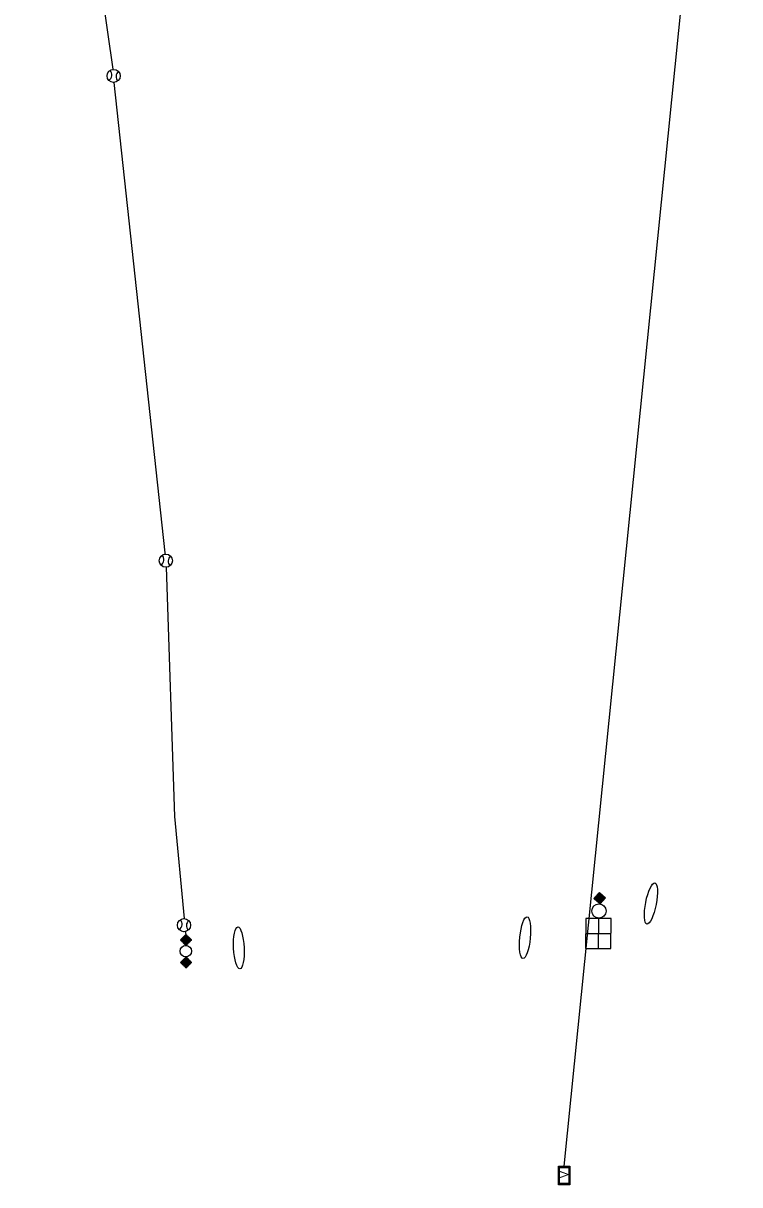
# Model space of a CAD drawing. Extents: x 584850 to 602551, y 145475 to 158627.
# Drawn here: x 594140 to 594577, y 153187 to 153895 of the extents above; entities that cross this region are included whole.
import ezdxf

# ---------------------------------------------------------------- set-up
doc = ezdxf.new("R2010")
doc.units = 0
doc.layers.add('B_MISC', color=7, linetype='Continuous')
doc.layers.add('E_RDWY', color=7, linetype='Continuous')

# ---------------------------------------------------------------- blocks, each defined once
blk = doc.blocks.new('PB24X42')
at = {"layer": 'E_RDWY'}
blk.add_circle((0, 0), 2, dxfattribs=at)
for centre, start, end in [((-2.59, 0.09), 308.3742, 47.6044), ((2.73, 0.07), 134.4184, 228.4474)]:
    blk.add_arc(centre, 2, start, end, dxfattribs=at)

msp = doc.modelspace()

# ---------------------------------------------------------------- linework, layer by layer
at = {"layer": 'B_MISC'}
for p, q in [((594469.73, 153198.28), (594576.82, 154259.36)), ((594194.8, 153867.11), (594139.91, 154245.19)), ((594226.44, 153572.23), (594195.44, 153859.06)), ((594232.36, 153411.51), (594227.19, 153563.53)), ((594238.28, 153349.25), (594232.36, 153411.51)), ((594238.65, 153341.41), (594239.15, 153339.63))]:
    msp.add_line(p, q, dxfattribs=at)
msp.add_arc((594176.91, 153565.37), 50, 7.0373, 7.8773, dxfattribs=at)
at = {"layer": 'E_RDWY'}
for p, q in [((594487.9, 153361.49), (594494.96, 153361.96)), ((594488.18, 153361.81), (594494.64, 153362.24)), ((594488.22, 153361.21), (594488.18, 153361.81)), ((594488.46, 153362.13), (594494.32, 153362.52)), ((594488.54, 153360.93), (594488.46, 153362.13)), ((594488.74, 153362.45), (594494, 153362.8)), ((594488.86, 153360.65), (594488.74, 153362.45)), ((594489.02, 153362.77), (594493.68, 153363.07)), ((594489.18, 153360.37), (594489.02, 153362.77)), ((594489.3, 153363.08), (594493.36, 153363.35)), ((594489.5, 153360.09), (594489.3, 153363.08)), ((594489.58, 153363.4), (594493.04, 153363.63)), ((594489.82, 153359.81), (594489.58, 153363.4)), ((594489.86, 153363.72), (594492.72, 153363.91)), ((594490.14, 153359.53), (594489.86, 153363.72)), ((594490.14, 153364.04), (594492.41, 153364.19)), ((594490.46, 153359.25), (594490.14, 153364.04)), ((594490.42, 153364.36), (594492.09, 153364.47)), ((594490.78, 153358.97), (594490.42, 153364.36)), ((594490.7, 153364.68), (594491.77, 153364.75)), ((594491.1, 153358.69), (594490.7, 153364.68)), ((594490.98, 153365), (594491.45, 153365.03)), ((594491.42, 153358.41), (594490.98, 153365)), ((594491.73, 153358.26), (594491.27, 153365.19)), ((594492.01, 153358.58), (594491.58, 153364.91)), ((594492.29, 153358.9), (594491.9, 153364.63)), ((594492.56, 153359.22), (594492.22, 153364.35)), ((594492.84, 153359.54), (594492.54, 153364.07)), ((594493.12, 153359.86), (594492.86, 153363.79)), ((594493.4, 153360.18), (594493.18, 153363.51)), ((594493.68, 153360.5), (594493.5, 153363.23)), ((594493.96, 153360.82), (594493.82, 153362.95)), ((594494.24, 153361.14), (594494.14, 153362.68)), ((594494.52, 153361.46), (594494.46, 153362.4)), ((594494.8, 153361.77), (594494.78, 153362.12)), ((594488.22, 153361.21), (594494.68, 153361.64)), ((594488.54, 153360.93), (594494.4, 153361.32)), ((594488.86, 153360.65), (594494.12, 153361)), ((594489.18, 153360.37), (594493.84, 153360.68)), ((594489.5, 153360.09), (594493.56, 153360.36)), ((594489.82, 153359.81), (594493.28, 153360.04)), ((594490.14, 153359.53), (594493, 153359.72)), ((594490.46, 153359.25), (594492.72, 153359.4)), ((594490.78, 153358.97), (594492.44, 153359.08)), ((594491.1, 153358.69), (594492.16, 153358.76)), ((594491.42, 153358.41), (594491.89, 153358.45)), ((594490.61, 153349.35), (594490.53, 153331)), ((594235.82, 153336.17), (594242.49, 153336.17)), ((594235.99, 153336.46), (594235.99, 153336.01)), ((594235.99, 153336.46), (594242.32, 153336.46)), ((594236.11, 153335.88), (594242.2, 153335.88)), ((594236.27, 153336.75), (594236.27, 153335.72)), ((594236.27, 153336.75), (594242.03, 153336.75)), ((594236.4, 153335.6), (594241.91, 153335.6)), ((594236.56, 153337.04), (594236.56, 153335.43)), ((594236.56, 153337.04), (594241.75, 153337.04)), ((594236.69, 153335.31), (594241.62, 153335.31)), ((594236.85, 153337.32), (594236.85, 153335.14)), ((594236.85, 153337.32), (594241.46, 153337.32)), ((594236.97, 153335.02), (594241.33, 153335.02)), ((594237.14, 153337.61), (594237.14, 153334.86)), ((594237.14, 153337.61), (594241.17, 153337.61)), ((594237.26, 153334.73), (594241.05, 153334.73)), ((594237.43, 153337.9), (594237.43, 153334.57)), ((594237.43, 153337.9), (594240.88, 153337.9)), ((594237.55, 153334.44), (594240.76, 153334.44)), ((594237.71, 153338.19), (594237.71, 153334.28)), ((594237.71, 153338.19), (594240.59, 153338.19)), ((594237.84, 153334.16), (594240.47, 153334.16)), ((594238, 153338.48), (594238, 153333.99)), ((594238, 153338.48), (594240.31, 153338.48)), ((594238.13, 153333.87), (594240.18, 153333.87)), ((594238.29, 153338.76), (594238.29, 153333.7)), ((594238.29, 153338.76), (594240.02, 153338.76)), ((594238.41, 153333.58), (594239.89, 153333.58)), ((594238.58, 153339.05), (594238.58, 153333.42)), ((594238.58, 153339.05), (594239.73, 153339.05)), ((594238.87, 153339.34), (594238.87, 153333.13)), ((594238.87, 153339.34), (594239.44, 153339.34)), ((594239.15, 153339.63), (594239.15, 153332.84)), ((594239.44, 153339.34), (594239.44, 153333.13)), ((594239.73, 153339.05), (594239.73, 153333.42)), ((594240.02, 153338.76), (594240.02, 153333.7)), ((594240.31, 153338.48), (594240.31, 153333.99)), ((594240.59, 153338.19), (594240.59, 153334.28)), ((594240.88, 153337.9), (594240.88, 153334.57)), ((594241.17, 153337.61), (594241.17, 153334.86)), ((594241.46, 153337.32), (594241.46, 153335.14)), ((594241.75, 153337.04), (594241.75, 153335.43)), ((594242.03, 153336.75), (594242.03, 153335.72)), ((594242.32, 153336.46), (594242.32, 153336.01)), ((594482.85, 153340.21), (594498.29, 153340.14)), ((594238.7, 153333.29), (594239.61, 153333.29)), ((594238.99, 153333), (594239.32, 153333)), ((594235.86, 153322.49), (594242.53, 153322.49)), ((594236.03, 153322.78), (594236.03, 153322.32)), ((594236.03, 153322.78), (594242.36, 153322.78)), ((594236.15, 153322.2), (594242.24, 153322.2)), ((594236.31, 153323.06), (594236.31, 153322.04)), ((594236.31, 153323.06), (594242.07, 153323.06)), ((594236.44, 153321.91), (594241.95, 153321.91)), ((594236.6, 153323.35), (594236.6, 153321.75)), ((594236.6, 153323.35), (594241.79, 153323.35)), ((594236.73, 153321.62), (594241.66, 153321.62)), ((594236.89, 153323.64), (594236.89, 153321.46)), ((594236.89, 153323.64), (594241.5, 153323.64)), ((594237.01, 153321.34), (594241.37, 153321.34)), ((594237.18, 153323.93), (594237.18, 153321.17)), ((594237.18, 153323.93), (594241.21, 153323.93)), ((594237.3, 153321.05), (594241.09, 153321.05)), ((594237.47, 153324.22), (594237.47, 153320.88)), ((594237.47, 153324.22), (594240.92, 153324.22)), ((594237.59, 153320.76), (594240.8, 153320.76)), ((594237.75, 153324.5), (594237.75, 153320.6)), ((594237.75, 153324.5), (594240.63, 153324.5)), ((594237.88, 153320.47), (594240.51, 153320.47)), ((594238.04, 153324.79), (594238.04, 153320.31)), ((594238.04, 153324.79), (594240.35, 153324.79)), ((594238.17, 153320.18), (594240.22, 153320.18)), ((594238.33, 153325.08), (594238.33, 153320.02)), ((594238.33, 153325.08), (594240.06, 153325.08)), ((594238.45, 153319.9), (594239.93, 153319.9)), ((594238.62, 153325.37), (594238.62, 153319.73)), ((594238.62, 153325.37), (594239.77, 153325.37)), ((594238.74, 153319.61), (594239.65, 153319.61)), ((594238.91, 153325.66), (594238.91, 153319.44)), ((594238.91, 153325.66), (594239.48, 153325.66)), ((594239.03, 153319.32), (594239.36, 153319.32)), ((594239.19, 153325.94), (594239.19, 153319.16)), ((594239.48, 153325.66), (594239.48, 153319.44)), ((594239.77, 153325.37), (594239.77, 153319.73)), ((594240.06, 153325.08), (594240.06, 153320.02)), ((594240.35, 153324.79), (594240.35, 153320.31)), ((594240.63, 153324.5), (594240.63, 153320.6)), ((594240.92, 153324.22), (594240.92, 153320.88)), ((594241.21, 153323.93), (594241.21, 153321.17)), ((594241.5, 153323.64), (594241.5, 153321.46)), ((594241.79, 153323.35), (594241.79, 153321.75)), ((594242.07, 153323.06), (594242.07, 153322.04)), ((594242.36, 153322.78), (594242.36, 153322.32))]:
    msp.add_line(p, q, dxfattribs=at)
for points in [[(594491.2, 153365.25), (594494.96, 153361.96), (594491.67, 153358.19), (594487.9, 153361.49)], [(594482.89, 153349.38), (594482.81, 153331.04), (594498.25, 153330.97), (594498.33, 153349.31)], [(594242.55, 153336.24), (594239.15, 153332.84), (594235.76, 153336.24), (594239.15, 153339.63)], [(594242.59, 153322.55), (594239.19, 153319.16), (594235.8, 153322.55), (594239.19, 153325.94)], [(594466.21, 153186.97), (594466.21, 153198.28), (594473.26, 153198.28), (594473.26, 153186.97)], [(594466.46, 153187.22), (594466.46, 153198.03), (594473.01, 153198.03), (594473.01, 153187.22)], [(594466.71, 153187.47), (594466.71, 153197.78), (594472.76, 153197.78), (594472.76, 153187.47)], [(594466.96, 153187.72), (594466.96, 153197.53), (594472.51, 153197.53), (594472.51, 153187.72)]]:
    msp.add_lwpolyline(points, close=True, dxfattribs=at)
for centre, radius in [((594490.94, 153353.89), 4.36), ((594239.01, 153329.37), 3.5)]:
    msp.add_circle(centre, radius, dxfattribs=at)
for centre, major_axis in [((594522.62, 153358.49), (-2.46, -12.58)), ((594445.9, 153337.67), (-1.24, -12.76)), ((594271.38, 153331.37), (0.58, -12.81))]:
    msp.add_ellipse(centre, major_axis=major_axis, ratio=0.249166, dxfattribs=at)

# ---------------------------------------------------------------- block references
at = {"layer": 'E_RDWY', "xscale": 2, "yscale": 2.0000000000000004, "rotation": -4.918194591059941}
for p in [(594195.03, 153863.08), (594226.86, 153567.51), (594237.94, 153345.26)]:
    msp.add_blockref('PB24X42', p, dxfattribs=at)

# ---------------------------------------------------------------- texts
at = {"layer": 'E_RDWY'}
msp.add_text('V', height=4.96, rotation=90, dxfattribs=at).set_placement((594472.21, 153191))

doc.saveas('drawing.dxf')
